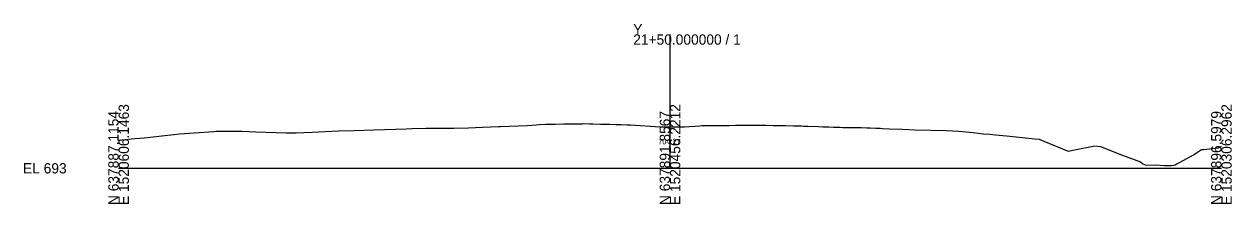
# Model space of a CAD drawing. Extents: x -26 to 303, y -10 to 5039.
# Drawn here: x -25.7 to 302.8, y 4990.3 to 5039.3 of the extents above; entities that cross this region are included whole.
import ezdxf

# ---------------------------------------------------------------- set-up
doc = ezdxf.new("R2010")
doc.units = 0
for name, color, linetype in [('Default', 7, 'Continuous'), ('Exist Cross Section Cell', 7, 'Continuous'), ('Exist XS Center Line Elevation Label', 7, 'Continuous'), ('Exist XS Ground Line', 7, 'Continuous')]:
    doc.layers.add(name, color=color, linetype=linetype)

msp = doc.modelspace()

# ---------------------------------------------------------------- linework, layer by layer
at = {"layer": 'Exist Cross Section Cell'}
for p, q in [((150, 5000), (150, 5036.47)), ((0, 5000), (150, 5000)), ((150, 5000), (300, 5000))]:
    msp.add_line(p, q, dxfattribs=at)
at = {"layer": 'Exist XS Ground Line'}
msp.add_lwpolyline([(0, 5007.66), (4.42, 5008.08), (6.94, 5008.34), (15.06, 5009.22), (16.53, 5009.38), (20.57, 5009.66), (25.89, 5010.03), (26.56, 5010.08), (32.94, 5010.07), (33.49, 5010.08), (37.37, 5009.94), (42.89, 5009.79), (45.71, 5009.68), (48.27, 5009.62), (50.39, 5009.77), (52.65, 5009.86), (59.84, 5010.18), (64.12, 5010.33), (69.42, 5010.51), (78.2, 5010.77), (79.76, 5010.81), (83.57, 5010.92), (91.18, 5010.93), (95.19, 5010.98), (99.01, 5011.16), (103.37, 5011.39), (103.93, 5011.39), (106.26, 5011.44), (108.74, 5011.56), (111.19, 5011.7), (113.57, 5011.84), (114.54, 5011.94), (116.11, 5011.99), (118.72, 5012.02), (121.07, 5012.07), (123.85, 5012.11), (126.12, 5012.15), (126.45, 5012.16), (128.1, 5012.13), (128.54, 5012.12), (128.99, 5012.11), (131.05, 5012.06), (132.96, 5012.01), (133.55, 5012), (135.39, 5011.94), (136.05, 5011.92), (136.71, 5011.91), (138.37, 5011.86), (139.28, 5011.85), (147.3, 5011.25), (150, 5011.27), (151.94, 5011.29), (153.94, 5011.3), (158.15, 5011.6), (158.64, 5011.63), (161.08, 5011.66), (163.18, 5011.7), (163.54, 5011.7), (163.98, 5011.7), (166.1, 5011.7), (167.78, 5011.72), (168.59, 5011.73), (169.35, 5011.73), (171.08, 5011.73), (172.93, 5011.74), (173.58, 5011.75), (173.95, 5011.75), (174.71, 5011.76), (175.69, 5011.74), (176.07, 5011.73), (178.09, 5011.7), (178.57, 5011.69), (179.03, 5011.68), (181.08, 5011.64), (181.44, 5011.64), (183.58, 5011.59), (185.75, 5011.53), (186.35, 5011.5), (187.06, 5011.47), (187.53, 5011.45), (190.4, 5011.34), (191.55, 5011.3), (192.09, 5011.28), (192.75, 5011.27), (193.22, 5011.26), (194.49, 5011.21), (196.31, 5011.16), (196.99, 5011.15), (198.73, 5011.12), (199.48, 5011.11), (201.15, 5011.08), (201.98, 5011.07), (203.58, 5011.01), (204.47, 5010.99), (205.99, 5010.93), (207.2, 5010.89), (207.77, 5010.88), (209.75, 5010.79), (213.13, 5010.65), (216.66, 5010.52), (225.15, 5010.25), (228.59, 5010.13), (232.45, 5009.78), (235.17, 5009.43), (236.97, 5009.29), (238.51, 5009.08), (241.58, 5008.8), (247.63, 5008.22), (249.16, 5008.05), (250.4, 5007.92), (251.72, 5007.37), (258.27, 5004.66), (260.5, 5005.11), (265.61, 5006.16), (267.15, 5005.96), (272.86, 5003.7), (278.02, 5001.77), (278.59, 5001.19), (279.51, 5000.87), (282.25, 5000.9), (284.48, 5000.74), (286.37, 5000.8), (286.97, 5000.88), (287.4, 5000.98), (287.91, 5001.25), (288.79, 5001.64), (292.37, 5003.68), (294.59, 5005.09), (295.16, 5005.15), (299.17, 5005.57), (300, 5006.04)], dxfattribs=at)

# ---------------------------------------------------------------- texts
at = {"layer": 'Default'}
msp.add_text('-', height=0.0001, dxfattribs=at).set_placement((0, 5000))
at = {"layer": 'Exist Cross Section Cell'}
for s, p in [('Y', (140, 5036.47)), ('21+50.000000 / 1', (140, 5033.67)), ('EL 693', (-26, 4998.6))]:
    msp.add_text(s, height=2.8, dxfattribs=at).set_placement(p)
for s, p in [('E 1520606.1463', (2.8, 4990)), ('E 1520456.2212', (152.8, 4990)), ('E 1520306.2962', (302.8, 4990)), ('N 637887.1154', (0, 4990)), ('N 637891.8567', (150, 4990)), ('N 637896.5979', (300, 4990))]:
    msp.add_text(s, height=2.8, rotation=90, dxfattribs=at).set_placement(p)
at = {"layer": 'Exist XS Center Line Elevation Label'}
msp.add_text('704.27', height=1.5, dxfattribs=at).set_placement((146.78, 5006.52))

doc.saveas('drawing.dxf')
